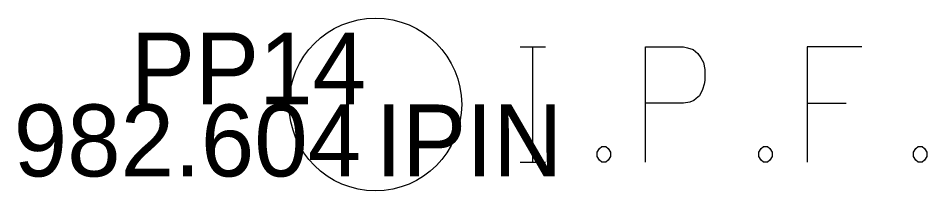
# Model space of a CAD drawing. Extents: x 2048206 to 2051708, y 354200 to 357644.
# Drawn here: x 2048768.95 to 2048781.59, y 355586.32 to 355588.72 of the extents above; entities that cross this region are included whole.
import ezdxf

# ---------------------------------------------------------------- set-up
doc = ezdxf.new("R2010")
doc.units = 0
for name, color, linetype in [('_CIVIL_CONSTRUCTION', 7, 'Continuous'), ('RW_X_CL_100_Bearings', 7, 'Continuous'), ('SV_P_Control_Cells_Set', 7, 'Continuous'), ('SV_P_Mon_Cells_Set', 7, 'Continuous')]:
    doc.layers.add(name, color=color, linetype=linetype)

msp = doc.modelspace()

# ---------------------------------------------------------------- linework, layer by layer
at = {"layer": 'RW_X_CL_100_Bearings'}
for points in [[(2048775.932, 355588.318), (2048776.285, 355588.318)], [(2048776.109, 355586.718), (2048776.109, 355588.318)], [(2048777.674, 355586.718), (2048777.674, 355588.318), (2048778.203, 355588.318), (2048778.258, 355588.305), (2048778.335, 355588.28), (2048778.369, 355588.255), (2048778.402, 355588.229), (2048778.446, 355588.167), (2048778.479, 355588.103), (2048778.501, 355588.003), (2048778.501, 355587.851), (2048778.49, 355587.801), (2048778.468, 355587.726), (2048778.424, 355587.637), (2048778.379, 355587.6), (2048778.346, 355587.574), (2048778.291, 355587.549), (2048778.203, 355587.537), (2048777.674, 355587.537)], [(2048780.683, 355588.318), (2048779.923, 355588.318), (2048779.923, 355586.718)], [(2048779.923, 355587.537), (2048780.463, 355587.537)], [(2048777.068, 355586.932), (2048777.123, 355586.932), (2048777.156, 355586.907), (2048777.189, 355586.856), (2048777.189, 355586.793), (2048777.156, 355586.743), (2048777.123, 355586.718), (2048777.068, 355586.718), (2048777.035, 355586.743), (2048777.002, 355586.793), (2048777.002, 355586.856), (2048777.035, 355586.907), (2048777.068, 355586.932)], [(2048779.317, 355586.932), (2048779.372, 355586.932), (2048779.405, 355586.907), (2048779.438, 355586.856), (2048779.438, 355586.793), (2048779.405, 355586.743), (2048779.372, 355586.718), (2048779.317, 355586.718), (2048779.283, 355586.743), (2048779.25, 355586.793), (2048779.25, 355586.856), (2048779.283, 355586.907), (2048779.317, 355586.932)], [(2048781.466, 355586.932), (2048781.521, 355586.932), (2048781.554, 355586.907), (2048781.587, 355586.856), (2048781.587, 355586.793), (2048781.554, 355586.743), (2048781.521, 355586.718), (2048781.466, 355586.718), (2048781.433, 355586.743), (2048781.4, 355586.793), (2048781.4, 355586.856), (2048781.433, 355586.907), (2048781.466, 355586.932)], [(2048775.932, 355586.718), (2048776.285, 355586.718)]]:
    msp.add_lwpolyline(points, dxfattribs=at)
msp.add_circle((2048773.918, 355587.518), 1.2, dxfattribs=at)

# ---------------------------------------------------------------- texts
at = {"layer": '_CIVIL_CONSTRUCTION'}
msp.add_text('IPIN', height=1, dxfattribs=at).set_placement((2048773.918, 355586.518))
at = {"layer": 'SV_P_Control_Cells_Set'}
msp.add_text('PP14', height=1, dxfattribs=at).set_placement((2048770.517, 355587.518))
at = {"layer": 'SV_P_Mon_Cells_Set'}
msp.add_text('982.604', height=1, dxfattribs=at).set_placement((2048768.887, 355586.518))

doc.saveas('drawing.dxf')
